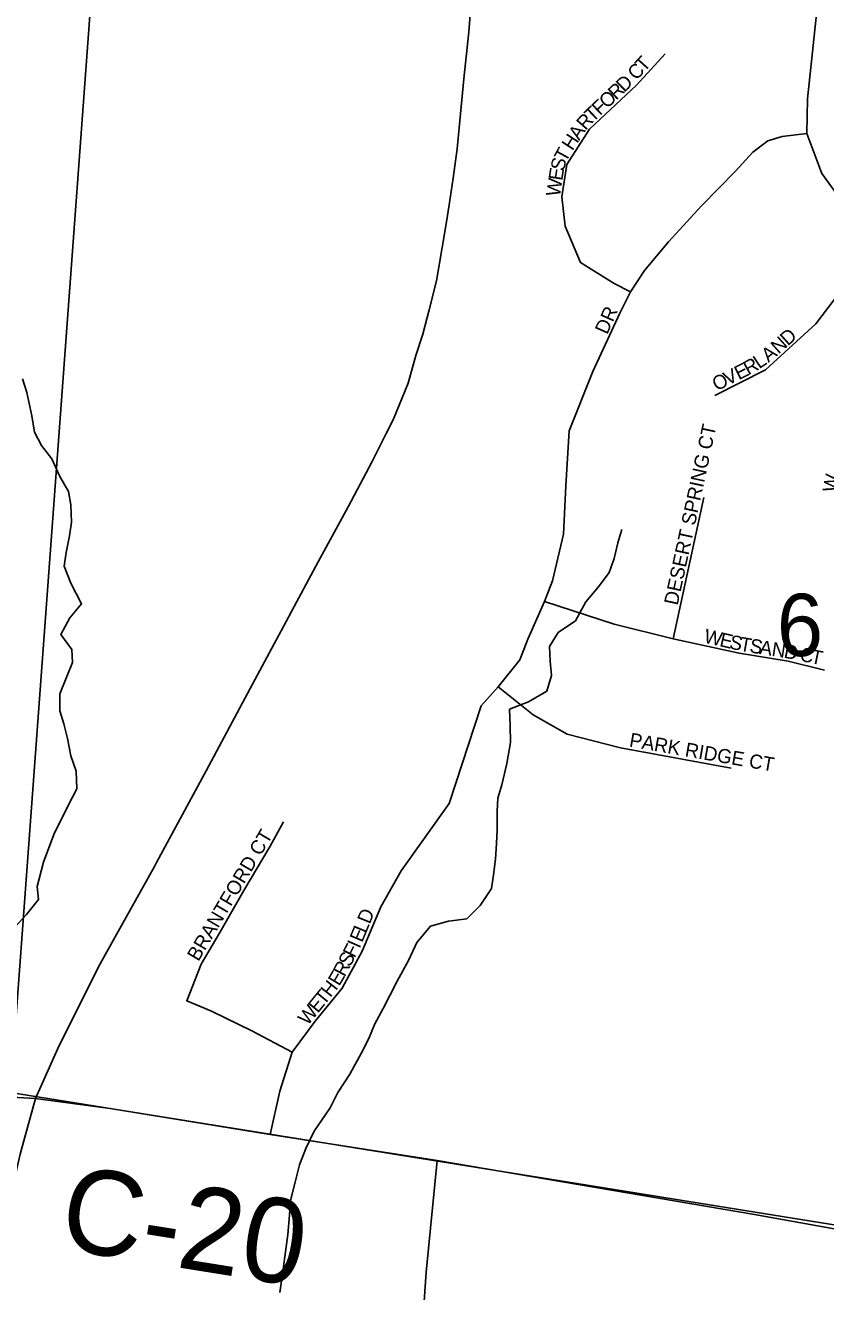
# Model space of a CAD drawing. Extents: x 1310247 to 1552180, y 377264 to 706493.
# Drawn here: x 1414286 to 1417129, y 501626 to 506121 of the extents above; entities that cross this region are included whole.
import ezdxf

# ---------------------------------------------------------------- set-up
doc = ezdxf.new("R2010")
doc.units = 0
for name, color, linetype in [('GM_X_County_Road', 7, 'Continuous'), ('GM_X_County_Road_Text', 7, 'Continuous'), ('GM_X_Minor_River', 7, 'Continuous'), ('GM_X_Section', 7, 'Continuous'), ('GM_X_Section_Text', 7, 'Continuous'), ('GM_X_State_Route', 7, 'Continuous'), ('GM_X_Township_Subdivision', 7, 'Continuous'), ('GM_X_Township_Subdivision_Text', 7, 'Continuous')]:
    doc.layers.add(name, color=color, linetype=linetype)

msp = doc.modelspace()

# ---------------------------------------------------------------- linework, layer by layer
at = {"layer": 'GM_X_County_Road'}
for points in [[(1413742.6, 502262.9), (1413842.3, 502272.3), (1414095.1, 502310.8), (1414196.2, 502318.5), (1414322.3, 502311.3)], [(1414322.3, 502311.3), (1414587.7, 502276.3), (1415155.6, 502183.5), (1415749, 502091.3)], [(1416374.7, 498013.1), (1416409.8, 498466.1), (1416422.9, 498695.6), (1416406.6, 498783.5), (1416345.5, 498901.5), (1416247.5, 499081.5), (1415646, 500629.8), (1415640.6, 500714), (1415641.5, 500825), (1415665.7, 501056.9), (1415709.6, 501695.5), (1415749, 502091.3)], [(1415749, 502091.3), (1416875.5, 501900.5), (1417651.8, 501760.2), (1419484.2, 501475.1), (1419792.8, 501418.4), (1420274, 501304.1), (1420497, 501249.5), (1421128.3, 501105.3), (1421506.2, 501017.5), (1421826.8, 500944.1), (1423039.1, 500645.1), (1423316.3, 500584.1), (1423856.7, 500469), (1424610.8, 500293.5), (1424806.2, 500257.1), (1425380.7, 500252.2)]]:
    msp.add_lwpolyline(points, dxfattribs=at)
at = {"layer": 'GM_X_Minor_River'}
for points in [[(1414249.6, 502920.5), (1414291.1, 502965.4), (1414332.8, 503018.3), (1414328.1, 503064.6), (1414350.7, 503150.2), (1414387.7, 503249.4), (1414438.9, 503352.2), (1414468.8, 503411.5), (1414466.6, 503473.8), (1414448.1, 503528.6), (1414435.9, 503589.1), (1414423.4, 503641.7), (1414408.7, 503688.3), (1414408.5, 503748.5), (1414434.3, 503810), (1414453.9, 503859.5), (1414451.2, 503905.8), (1414412.7, 503959.1), (1414444.5, 504018.4), (1414486.1, 504067.3), (1414448.1, 504140.7), (1414423.8, 504201.6), (1414431.2, 504249.6), (1414443, 504309.4), (1414450.5, 504357.4), (1414448.3, 504419.7), (1414439.6, 504466.1), (1414409.1, 504519.2), (1414380.8, 504582.3), (1414344.1, 504629.6), (1414319.4, 504676.5), (1414309.1, 504735), (1414291.5, 504817.8), (1414276.8, 504866.4)], [(1415190.7, 501623.4), (1415200.9, 501697.3), (1415208.5, 501749.3), (1415218.9, 501829.2), (1415224.9, 501897.3), (1415228.4, 501949.3), (1415244.4, 502015.1), (1415260.3, 502076.8), (1415282, 502134.3), (1415312, 502195.6), (1415368.6, 502278.2), (1415396.3, 502333.6), (1415438.3, 502398.5), (1415480.7, 502473.5), (1415506.3, 502524.9), (1415527.9, 502576.4), (1415557.6, 502631.7), (1415581, 502677.1), (1415606.6, 502728.5), (1415646.9, 502801.6), (1415676.9, 502864.9), (1415724.7, 502923.6), (1415789.5, 502941.7), (1415854, 502949.8), (1415901.5, 502996.5), (1415941.4, 503057.5), (1415948.9, 503105.4), (1415956.5, 503161.4), (1415960.2, 503217.5), (1415961.6, 503265.6), (1415961.5, 503331.8), (1415964.9, 503377.9), (1415978.4, 503425.7), (1415996.6, 503501.4), (1416008.9, 503575.2), (1416008.6, 503635.5), (1416006.3, 503693.7), (1416073.3, 503719.8), (1416138.7, 503757.9), (1416154.4, 503813.6), (1416149.8, 503864), (1416147.3, 503916.2), (1416178.9, 503965.4), (1416240.4, 504007.7), (1416276.4, 504074.8), (1416322.1, 504127.6), (1416359.8, 504178.7), (1416377.3, 504228.3), (1416391, 504284.1), (1416404.4, 504331.8)]]:
    msp.add_lwpolyline(points, dxfattribs=at)
at = {"layer": 'GM_X_Section'}
for points in [[(1414533.6, 506397), (1414234.1, 502333.5), (1408766.1, 501397.1), (1409190.5, 506806)], [(1414533.6, 506397), (1419763.1, 506010.4), (1419420.1, 501499.9), (1414234.1, 502333.5)], [(1419420.1, 501499.9), (1419004.7, 496044.9), (1413821.6, 496918.4), (1414234.1, 502333.5)]]:
    msp.add_lwpolyline(points, close=True, dxfattribs=at)
at = {"layer": 'GM_X_State_Route'}
for points in [[(1415805.5, 505579.3), (1415820.4, 505682.5), (1415843.7, 505931.8), (1415861.8, 506098.3), (1415877.6, 506308.5)], [(1415781.9, 505424), (1415791.7, 505483.6), (1415805.5, 505579.3)], [(1415568.3, 504671.8), (1415592.8, 504720.4), (1415645.6, 504850.8), (1415672.7, 504949.4), (1415698.3, 505025), (1415721.1, 505111.3), (1415746.6, 505214.6), (1415766.9, 505332.2), (1415781.9, 505424)], [(1415223.2, 504025.2), (1415326.9, 504217.2), (1415433.1, 504411.5), (1415518.3, 504572.7), (1415568.3, 504671.8)], [(1414752.7, 503148.9), (1414929.1, 503474.4), (1415085.1, 503767.4), (1415220.7, 504020.5), (1415223.2, 504025.2)], [(1414599.1, 502874.9), (1414745.3, 503135.3), (1414752.7, 503148.9)], [(1414322.3, 502311.3), (1414406.3, 502499.5), (1414551.7, 502790.3), (1414599.1, 502874.9)], [(1414240.5, 501992.7), (1414250.4, 502036.2), (1414267.7, 502114.5), (1414285, 502174.8), (1414322.3, 502311.3)]]:
    msp.add_lwpolyline(points, dxfattribs=at)
at = {"layer": 'GM_X_Township_Subdivision'}
for points in [[(1418167.1, 502818.4), (1418207, 503269.3), (1418248.8, 503665.6), (1418242.9, 503870.8), (1418219, 504111.8), (1418201.1, 504305), (1418151.4, 504444.3), (1418049.4, 504569.3), (1417895.2, 504737.9), (1417635.5, 505021.7), (1417520, 505148), (1417339.1, 505339.1), (1417173.6, 505513.9), (1417115.3, 505595.6), (1417062.1, 505737), (1417063.8, 505860.4), (1417102.2, 506217.1)], [(1416434.9, 505175.3), (1416377, 505204.9), (1416257.6, 505279.3), (1416203.9, 505408.4), (1416192, 505511.9), (1416209.9, 505627.5), (1416289.5, 505753), (1416457.2, 505908.7), (1416558.3, 506019.9)], [(1417846.6, 505806.7), (1417339.1, 505339.1), (1417205.5, 505209.2), (1417094, 505061.9), (1416914.8, 504898.5), (1416735.3, 504806.8)], [(1415155.6, 502183.5), (1415190.4, 502337.2), (1415234.2, 502476.6), (1415315.8, 502586.1), (1415411.4, 502703.7), (1415483.1, 502835.1), (1415548.8, 502992.4), (1415620.5, 503119.9), (1415791.7, 503358.9), (1415905.2, 503705.5), (1415965, 503773.2), (1416042.6, 503868.8), (1416070.5, 503942.5), (1416130.2, 504075.9), (1416158.1, 504149.6), (1416197.9, 504314.9), (1416205.9, 504486.2), (1416217.8, 504681.4), (1416301.4, 504892.5), (1416397, 505099.7), (1416434.9, 505175.3), (1416484.6, 505251), (1416569.9, 505353.3), (1416687.3, 505480.1), (1416808.1, 505604.1), (1416870.3, 505671.2), (1416922.6, 505710.9), (1416973.5, 505726.9), (1417062.1, 505737)], [(1416587.5, 503943.7), (1416695.7, 504445.7)], [(1416130.2, 504075.9), (1416377.4, 503995.1), (1416587.5, 503943.7), (1416821, 503892.3), (1416995.5, 503864.6), (1417124.4, 503832.3)], [(1415965, 503773.2), (1416089.8, 503674), (1416210.4, 503604.6), (1416400, 503556.1), (1416793.3, 503484.4)], [(1415234.2, 502476.6), (1415091.1, 502551.7), (1414947.8, 502621.5), (1414859.6, 502658.8), (1414911.3, 502788.9), (1414976.9, 502900.4), (1415062.4, 503050.1), (1415156.3, 503207.9), (1415203.4, 503293.4)]]:
    msp.add_lwpolyline(points, dxfattribs=at)

# ---------------------------------------------------------------- texts
at = {"layer": 'GM_X_County_Road_Text'}
msp.add_text('C-20', height=300, rotation=350.9156, dxfattribs=at).set_placement((1414399.6, 501780.6))
at = {"layer": 'GM_X_Section_Text'}
msp.add_text('6', height=221, rotation=0, dxfattribs=at).set_placement((1416955.1, 503882.4))
at = {"layer": 'GM_X_Township_Subdivision_Text'}
for s, rotation, p in [('T', 47.8664, (1416483.7, 505953)), ('C', 47.3222, (1416456.5, 505923.5)), ('R', 43.4846, (1416384.2, 505853.7)), ('D', 43.8208, (1416413.2, 505881.2)), ('F', 43.4832, (1416326.8, 505799.2)), ('O', 43.4864, (1416352.3, 505823.4)), ('T', 43.8214, (1416301.4, 505774.9)), ('R', 48.8323, (1416276.2, 505745.9)), ('H', 57.0737, (1416229.2, 505673.7)), ('A', 56.6706, (1416253.1, 505710.6)), ('T', 61.3209, (1416205.8, 505632.5)), ('S', 75.8279, (1416198.4, 505601.5)), ('E', 81.2923, (1416193.3, 505567.9)), ('W', 81.2992, (1416184.6, 505511.4)), ('DR', 66.0386, (1416352.6, 505021.1)), ('N', 41.7622, (1416961.3, 504952)), ('D', 41.7622, (1416994.2, 504981.3)), ('A', 39.2289, (1416925.4, 504922.6)), ('E', 26.5629, (1416820.1, 504861.3)), ('R', 29.0961, (1416853.7, 504878.1)), ('L', 34.1625, (1416892.4, 504899.9)), ('O', 26.5629, (1416741.4, 504821.9)), ('V', 26.5629, (1416780.7, 504841.6)), ('DESERT SPRING CT', 77.8112, (1416602.8, 504060.1)), ('W', 78.8681, (1417165.9, 504460.1)), ('W', 346.9159, (1416693.3, 503930.9)), ('E', 346.9081, (1416749, 503917.9)), ('S', 347.3833, (1416783.7, 503909.8)), ('T', 350.006, (1416820.5, 503901.6)), ('S', 351.1609, (1416856.3, 503895.4)), ('A', 351.2224, (1416891.1, 503889.9)), ('N', 351.2239, (1416934.6, 503883.2)), ('D', 349.5837, (1416977.7, 503876.6)), ('C', 348.3352, (1417033.7, 503866)), ('T', 348.3069, (1417072.4, 503858)), ('PARK RIDGE CT', 350.0875, (1416428.8, 503561.4)), ('BRANTFORD CT', 59.5069, (1414901, 502795.7)), ('D', 67.6158, (1415509.4, 502928.3)), ('E', 67.483, (1415482.5, 502863.1)), ('L', 67.6145, (1415496, 502895.7)), ('F', 62.9983, (1415455.9, 502807.7)), ('I', 66.2574, (1415473.2, 502841.9)), ('R', 61.9031, (1415420.2, 502740.8)), ('S', 62.0172, (1415438.9, 502775.8)), ('E', 59.3301, (1415401, 502708.3)), ('H', 51.909, (1415369.9, 502667.9)), ('E', 50.9909, (1415325.1, 502612.5)), ('T', 50.9997, (1415347.2, 502639.8)), ('W', 50.991, (1415289.1, 502568))]:
    msp.add_text(s, height=50, rotation=rotation, dxfattribs=at).set_placement(p)

doc.saveas('drawing.dxf')
